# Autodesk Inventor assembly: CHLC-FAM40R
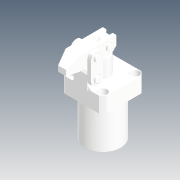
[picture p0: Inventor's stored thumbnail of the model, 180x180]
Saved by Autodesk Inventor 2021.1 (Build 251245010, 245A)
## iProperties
Company: Microsoft
Created: 2019-11
Part Number: CHLC-FAM40R
Description: STEP AP214
Document SubType Name: Assembly
Designer: user
Title: CHLC-FAM40R.STEP
Author: Windows
Revision Number: ÈÎºÎ
Sending System: SolidWorks 2015
Preprocessor: SwSTEP 2.0
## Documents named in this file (11)
- D:\Vault_2016\Projekty\Clamptek\Hydraulic\CHLC\CHLC-40\Inventor\CHLC-FAM40R\CHLC-FAM40R.iam
- D:\Vault_2016\Projekty\Clamptek\Hydraulic\CHLC\CHLC-40\Inventor\CHLC-FAM40R\CHLC-FAM40±¾Ìå.ipt
- D:\Vault_2016\Projekty\Clamptek\Hydraulic\CHLC\CHLC-40\Inventor\CHLC-FAM40R\CHLC-40-01_1.ipt
- D:\Vault_2016\Projekty\Clamptek\Hydraulic\CHLC\CHLC-40\Inventor\CHLC-FAM40R\CHLC-40-02_1.ipt
- D:\Vault_2016\Projekty\Clamptek\Hydraulic\CHLC\CHLC-40\Inventor\CHLC-FAM40R\CHLC-40-03_1.ipt
- D:\Vault_2016\Projekty\Clamptek\Hydraulic\CHLC\CHLC-40\Inventor\CHLC-FAM40R\CHLC-40-04_1.ipt
- D:\Vault_2016\Projekty\Clamptek\Hydraulic\CHLC\CHLC-40\Inventor\CHLC-FAM40R\CHLC-40-06_1.ipt
- D:\Vault_2016\Projekty\Clamptek\Hydraulic\CHLC\CHLC-40\Inventor\CHLC-FAM40R\CHLC-40-08_1.ipt
- D:\Vault_2016\Projekty\Clamptek\Hydraulic\CHLC\CHLC-40\Inventor\CHLC-FAM40R\HANJIE.ipt
- D:\Vault_2016\Projekty\Clamptek\Hydraulic\CHLC\CHLC-40\Inventor\CHLC-FAM40R\ZHICHENGKUAI.ipt
- D:\Vault_2016\Projekty\Clamptek\Hydraulic\CHLC\CHLC-40\Inventor\CHLC-FAM40R\M6LS_1.ipt
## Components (18 placed, 18 different names)
1. CHLC-FAM40±¾Ìå_1
2. CHLC-40-01_1_2
3. CHLC-40-02_1_3
4. CHLC-40-03_1_4
5. CHLC-40-04_1_5
6. CHLC-40-06_1_6
7. CHLC-40-08_1_7
8. HANJIE_8
9. ZHICHENGKUAI_9
10. CHLC-40-03_1_10
11. CHLC-40-06_1_11
12. CHLC-40-06_1_12
13. CHLC-40-06_1_13
14. CHLC-40-06_1_14
15. CHLC-40-06_1_15
16. CHLC-40-02_1_16
17. M6LS_1_17
18. M6LS_1_18
